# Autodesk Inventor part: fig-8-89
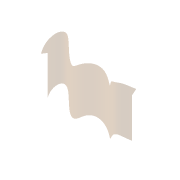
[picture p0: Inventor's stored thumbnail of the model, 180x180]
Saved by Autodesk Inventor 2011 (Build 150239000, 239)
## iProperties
Shininess: 64.0
Length Units: 11269
Angle Units: 11279
Time Units: 11290
Mass Units: 11283
Length Display Precision: 3
Angle Display Precision: 2
Compacted: True
Part Number: fig-8-89
Document SubType Name: Modeling
Created: 2003-08
Designer: Owner
Manufacturer: Standard
Standards Organization: Custom
Density: 1 g/cm^3
Density: 0.0
Volumn: 0.0
Area: 0.0
PropertySet Name: Model Information
Control State: 0
Master: False
Checked Out: False
Author: Owner
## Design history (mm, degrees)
sketch "Sketch1"
  geometry: 7 further points
  constraints: 7 other
  dimensions: "d0" = 80 horizontal distance of point (40, 1.742) point (-40, -4.065); "d1" = 40 horizontal distance of point (0, 0) point (-40, -4.065)
extrude_surface "ExtrusionSrf1" sketch "Sketch1" dims "d2" = 80, "d3" = 0
sketch "Sketch2"
  geometry: L1 (40, 0)-(40, -40) reference; L2 (-40, 0)-(-40, -40) reference; 7 further points
  constraints: 2 point on line, 7 other
extrude_surface "ExtrusionSrf2" dims "d4" = 80, "d5" = 0
split "Split6"
sketch "3D Sketch1"
feature "SweepSrf1" sketch "3D Sketch1" dims "d6" = 0
feature "Extend1" dims "d7" = 10
body "Srf1"
body "Srf2"
body "Srf3"
node "3D Intersection1"
